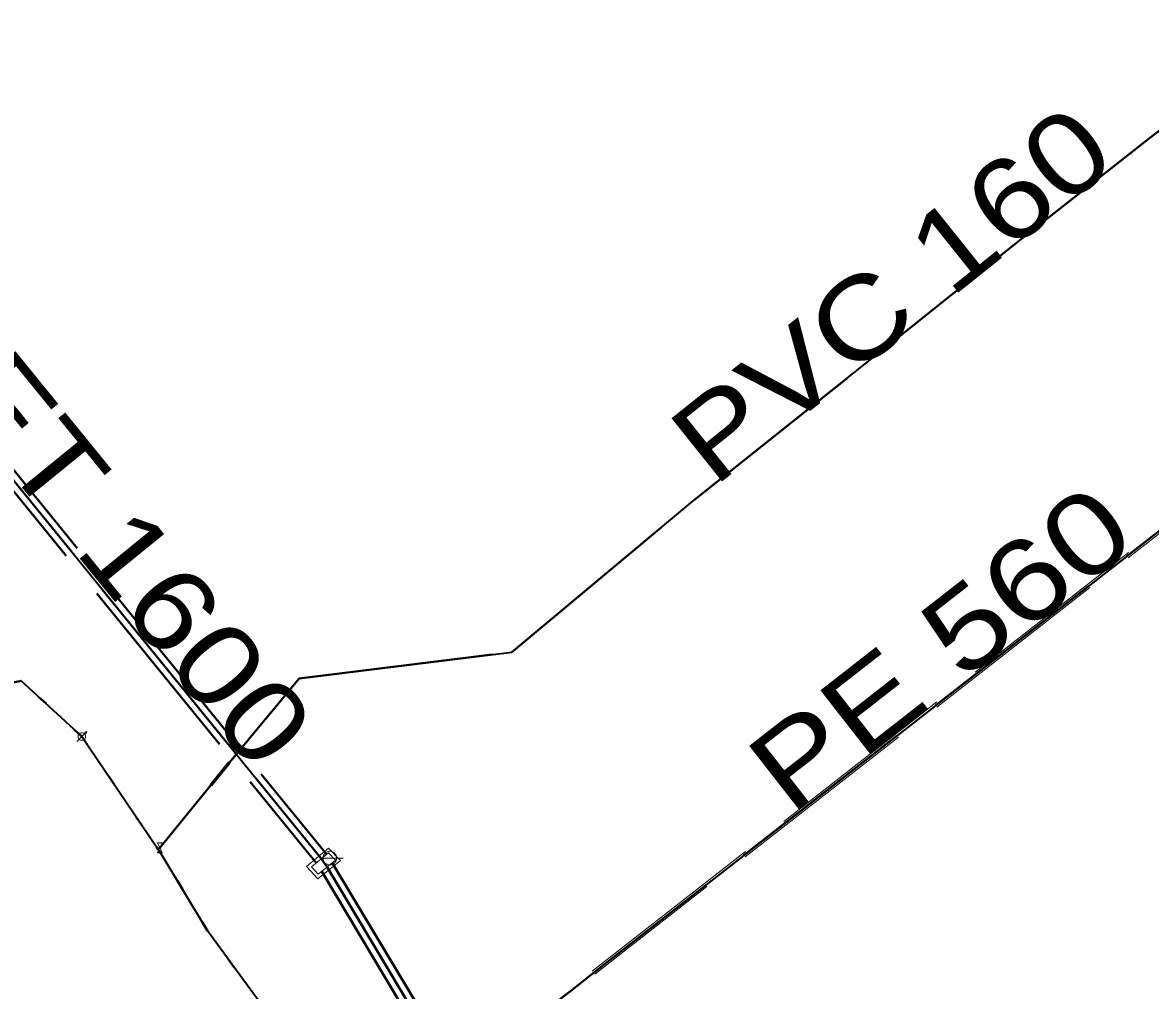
# Model space of a CAD drawing. Extents: x -968691 to -140888, y -1376050 to -879856.
# Drawn here: x -647839.9 to -647672.7, y -1059240 to -1059096.6 of the extents above; entities that cross this region are included whole.
import ezdxf
from ezdxf.enums import TextEntityAlignment as Align

# ---------------------------------------------------------------- set-up
doc = ezdxf.new("R2010")
doc.units = 0
doc.header["$LTSCALE"] = 4.8
doc.linetypes.add('DOTTED', pattern=[1.5, 0.3, -1.2])
doc.linetypes.add('LONG_DASHED', pattern=[7.5, 6, -1.5])
doc.layers.add('1', color=7, linetype='Continuous', lineweight=13)

msp = doc.modelspace()

# ---------------------------------------------------------------- hatches: boundary and pattern name
at = {"layer": '1'}
msp.add_hatch(color=256, dxfattribs=at).paths.add_polyline_path([(-647819.398, -1059218.87), (-647819.4, -1059218.846), (-647819.407, -1059218.823), (-647819.417, -1059218.801), (-647819.431, -1059218.782), (-647819.449, -1059218.765), (-647819.469, -1059218.752), (-647819.492, -1059218.743), (-647819.515, -1059218.739), (-647819.539, -1059218.738), (-647819.563, -1059218.742), (-647819.586, -1059218.75), (-647819.607, -1059218.762), (-647819.625, -1059218.778), (-647819.64, -1059218.797), (-647819.652, -1059218.818), (-647819.659, -1059218.841), (-647819.662, -1059218.865), (-647819.661, -1059218.889), (-647819.655, -1059218.912), (-647819.645, -1059218.934), (-647819.632, -1059218.954), (-647819.615, -1059218.971), (-647819.595, -1059218.985), (-647819.573, -1059218.995), (-647819.55, -1059219.001), (-647819.526, -1059219.002), (-647819.502, -1059218.999), (-647819.479, -1059218.992), (-647819.458, -1059218.981), (-647819.439, -1059218.966), (-647819.423, -1059218.947), (-647819.411, -1059218.927), (-647819.402, -1059218.904), (-647819.398, -1059218.88)])

# ---------------------------------------------------------------- linework, layer by layer
at = {"layer": '1', "linetype": 'LONG_DASHED', "lineweight": 40}
for p, q in [((-647872.7, -1059124.22), (-647794.851, -1059219.843)), ((-647874.314, -1059125.35), (-647796.391, -1059221.12)), ((-647873.53, -1059124.73), (-647795.632, -1059220.469)), ((-647819.82, -1059219.08), (-647820.055, -1059218.748)), ((-647819.82, -1059219.08), (-647819.53, -1059218.87)), ((-647819.495, -1059219.538), (-647819.82, -1059219.08)), ((-647795.632, -1059220.469), (-647794.763, -1059221.744)), ((-647793.992, -1059221.085), (-647764.744, -1059269.917)), ((-647795.556, -1059222.364), (-647766.316, -1059271.182)), ((-647794.763, -1059221.744), (-647765.77, -1059270.15))]:
    msp.add_line(p, q, dxfattribs=at)
at = {"layer": '1', "lineweight": 35}
for p, q in [((-647873.53, -1059124.73), (-647795.632, -1059220.469)), ((-647831.099, -1059202.397), (-647820.055, -1059218.748)), ((-647819.82, -1059219.08), (-647820.055, -1059218.748)), ((-647819.82, -1059219.08), (-647819.53, -1059218.87)), ((-647819.495, -1059219.538), (-647819.82, -1059219.08)), ((-647795.632, -1059220.469), (-647794.763, -1059221.744)), ((-647794.763, -1059221.744), (-647765.77, -1059270.15))]:
    msp.add_line(p, q, dxfattribs=at)
at = {"layer": '1', "linetype": 'LONG_DASHED'}
for p, q in [((-647755.465, -1059237.144), (-647653.715, -1059157.694)), ((-647653.345, -1059158.166), (-647755.095, -1059237.616)), ((-647809.356, -1059206.145), (-647812.086, -1059209.515)), ((-647809.123, -1059206.334), (-647811.853, -1059209.704)), ((-647794.531, -1059218.928), (-647797.811, -1059221.649)), ((-647794.57, -1059219.61), (-647797.09, -1059221.7)), ((-647793.52, -1059220.7), (-647794.57, -1059219.61)), ((-647797.811, -1059221.649), (-647796.14, -1059223.487))]:
    msp.add_line(p, q, dxfattribs=at)
at = {"layer": '1'}
for p, q in [((-647831.832, -1059203.129), (-647830.368, -1059201.665)), ((-647830.702, -1059201.754), (-647830.368, -1059201.665)), ((-647830.458, -1059202), (-647830.368, -1059201.665)), ((-647795.358, -1059220.4), (-647792.382, -1059220.4))]:
    msp.add_line(p, q, dxfattribs=at)
at = {"layer": '1', "linetype": 'DOTTED', "lineweight": 40}
msp.add_line((-647831.099, -1059202.397), (-647820.055, -1059218.748), dxfattribs=at)
at = {"layer": '1', "linetype": 'LONG_DASHED', "lineweight": 40}
for points in [[(-647819.53, -1059218.87), (-647811.97, -1059209.61), (-647809.24, -1059206.24), (-647804.94, -1059201.07), (-647803.7, -1059199.58), (-647798.88, -1059193.79), (-647767.36, -1059189.87), (-647740.25, -1059167.27), (-647710.88, -1059143.86), (-647692.34, -1059129.04), (-647672.87, -1059113.72), (-647655.83, -1059100.67), (-647651.9, -1059097.57), (-647650.67, -1059096.59)], [(-647649.55, -1059154.88), (-647650.59, -1059155.74), (-647650.63, -1059155.82), (-647653.53, -1059157.93), (-647755.28, -1059237.38), (-647755.346, -1059237.446)], [(-647773.946, -1059251.688), (-647773.795, -1059251.618), (-647758.476, -1059239.995), (-647755.985, -1059237.965), (-647755.346, -1059237.446)]]:
    msp.add_lwpolyline(points, dxfattribs=at)
at = {"layer": '1', "lineweight": 35}
for points in [[(-647819.53, -1059218.87), (-647811.97, -1059209.61), (-647809.24, -1059206.24), (-647804.94, -1059201.07), (-647803.7, -1059199.58), (-647798.88, -1059193.79), (-647767.36, -1059189.87), (-647740.25, -1059167.27), (-647710.88, -1059143.86), (-647692.34, -1059129.04), (-647672.87, -1059113.72), (-647655.83, -1059100.67), (-647651.9, -1059097.57), (-647650.67, -1059096.59)], [(-647831.099, -1059202.397), (-647840.069, -1059194.127), (-647867.192, -1059200.266), (-647876.082, -1059149.482), (-647878.022, -1059147.34), (-647916.85, -1059098.69)], [(-647649.55, -1059154.88), (-647650.59, -1059155.74), (-647650.63, -1059155.82), (-647653.53, -1059157.93), (-647755.28, -1059237.38), (-647755.346, -1059237.446)], [(-647804.27, -1059242.41), (-647812.48, -1059231.18), (-647819.495, -1059219.538)], [(-647773.946, -1059251.688), (-647773.795, -1059251.618), (-647758.476, -1059239.995), (-647755.985, -1059237.965), (-647755.346, -1059237.446)]]:
    msp.add_lwpolyline(points, dxfattribs=at)
at = {"layer": '1', "linetype": 'DOTTED', "lineweight": 40}
for points in [[(-647831.099, -1059202.397), (-647840.069, -1059194.127), (-647867.192, -1059200.266), (-647876.082, -1059149.482), (-647878.022, -1059147.34), (-647916.85, -1059098.69)], [(-647804.27, -1059242.41), (-647812.48, -1059231.18), (-647819.495, -1059219.538)]]:
    msp.add_lwpolyline(points, dxfattribs=at)
at = {"layer": '1'}
for points in [[(-647830.54, -1059202.397), (-647830.549, -1059202.3), (-647830.574, -1059202.206), (-647830.615, -1059202.118), (-647830.671, -1059202.038), (-647830.74, -1059201.969), (-647830.82, -1059201.913), (-647830.908, -1059201.872), (-647831.002, -1059201.847), (-647831.099, -1059201.838), (-647831.196, -1059201.847), (-647831.291, -1059201.872), (-647831.379, -1059201.913), (-647831.459, -1059201.969), (-647831.528, -1059202.038), (-647831.583, -1059202.118), (-647831.625, -1059202.206), (-647831.65, -1059202.3), (-647831.658, -1059202.397), (-647831.65, -1059202.494), (-647831.625, -1059202.588), (-647831.583, -1059202.677), (-647831.528, -1059202.756), (-647831.459, -1059202.825), (-647831.379, -1059202.881), (-647831.291, -1059202.922), (-647831.196, -1059202.948), (-647831.099, -1059202.956), (-647831.002, -1059202.948), (-647830.908, -1059202.922), (-647830.82, -1059202.881), (-647830.74, -1059202.825), (-647830.671, -1059202.756), (-647830.615, -1059202.677), (-647830.574, -1059202.588), (-647830.549, -1059202.494)], [(-647819.88, -1059218.12), (-647819.18, -1059218.12), (-647819.88, -1059219.62), (-647819.18, -1059219.62)], [(-647819.398, -1059218.87), (-647819.4, -1059218.846), (-647819.407, -1059218.823), (-647819.417, -1059218.801), (-647819.431, -1059218.782), (-647819.449, -1059218.765), (-647819.469, -1059218.752), (-647819.492, -1059218.743), (-647819.515, -1059218.739), (-647819.539, -1059218.738), (-647819.563, -1059218.742), (-647819.586, -1059218.75), (-647819.607, -1059218.762), (-647819.625, -1059218.778), (-647819.64, -1059218.797), (-647819.652, -1059218.818), (-647819.659, -1059218.841), (-647819.662, -1059218.865), (-647819.661, -1059218.889), (-647819.655, -1059218.912), (-647819.645, -1059218.934), (-647819.632, -1059218.954), (-647819.615, -1059218.971), (-647819.595, -1059218.985), (-647819.573, -1059218.995), (-647819.55, -1059219.001), (-647819.526, -1059219.002), (-647819.502, -1059218.999), (-647819.479, -1059218.992), (-647819.458, -1059218.981), (-647819.439, -1059218.966), (-647819.423, -1059218.947), (-647819.411, -1059218.927), (-647819.402, -1059218.904), (-647819.398, -1059218.88)], [(-647794.35, -1059219.392), (-647794.455, -1059219.398), (-647794.559, -1059219.414), (-647794.661, -1059219.442), (-647794.76, -1059219.48), (-647794.854, -1059219.527), (-647794.942, -1059219.585), (-647795.024, -1059219.651), (-647795.099, -1059219.726), (-647795.165, -1059219.808), (-647795.223, -1059219.896), (-647795.27, -1059219.99), (-647795.308, -1059220.089), (-647795.336, -1059220.191), (-647795.352, -1059220.295), (-647795.358, -1059220.4), (-647795.352, -1059220.505), (-647795.336, -1059220.61), (-647795.308, -1059220.712), (-647795.27, -1059220.81), (-647795.223, -1059220.904), (-647795.165, -1059220.993), (-647795.099, -1059221.075), (-647795.024, -1059221.149), (-647794.942, -1059221.215), (-647794.854, -1059221.273), (-647794.76, -1059221.321), (-647794.661, -1059221.359), (-647794.559, -1059221.386), (-647794.455, -1059221.402), (-647794.35, -1059221.408), (-647794.245, -1059221.402), (-647794.14, -1059221.386), (-647794.038, -1059221.359), (-647793.94, -1059221.321), (-647793.846, -1059221.273), (-647793.757, -1059221.215), (-647793.675, -1059221.149), (-647793.601, -1059221.075), (-647793.535, -1059220.993), (-647793.477, -1059220.904), (-647793.429, -1059220.81), (-647793.391, -1059220.712), (-647793.364, -1059220.61), (-647793.348, -1059220.505), (-647793.342, -1059220.4), (-647793.348, -1059220.295), (-647793.364, -1059220.191), (-647793.391, -1059220.089), (-647793.429, -1059219.99), (-647793.477, -1059219.896), (-647793.535, -1059219.808), (-647793.601, -1059219.726), (-647793.675, -1059219.651), (-647793.757, -1059219.585), (-647793.846, -1059219.527), (-647793.94, -1059219.48), (-647794.038, -1059219.442), (-647794.14, -1059219.414), (-647794.245, -1059219.398)]]:
    msp.add_lwpolyline(points, close=True, dxfattribs=at)
at = {"layer": '1', "linetype": 'LONG_DASHED'}
for points in [[(-647796.14, -1059223.487), (-647792.783, -1059220.744), (-647794.531, -1059218.928)], [(-647797.09, -1059221.7), (-647796.09, -1059222.8), (-647793.52, -1059220.7)]]:
    msp.add_lwpolyline(points, dxfattribs=at)

# ---------------------------------------------------------------- texts
at = {"layer": '1'}
for s, rotation, width, p in [('PVC 160', 38.639, 1.2, (-647707.359, -1059141.52)), ('BET 1600', 309.134, 1.2, (-647832.326, -1059174.895)), ('PE 560', 37.965, 1.25, (-647700.177, -1059194.003))]:
    msp.add_text(s, height=12, rotation=rotation, dxfattribs=dict(at, width=width)).set_placement(p, align=Align.CENTER)

doc.saveas('drawing.dxf')
